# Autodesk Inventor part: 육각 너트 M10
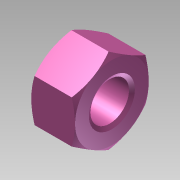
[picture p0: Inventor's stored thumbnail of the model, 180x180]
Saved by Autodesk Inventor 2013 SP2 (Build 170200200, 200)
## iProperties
Created: 2025-04
Part Number: 육각 너트 M10
Material: Generic
Document SubType Name: Modeling
Designer: i
Density: 1 g/cm^3
변환 표준: STEP AP214IS
전처리기: Build: 200, Release: 2013 SP2 Update 6 - Date: Thu 07/17/2014
전송 단위: 밀리미터
불확실성: 0.01
Author: i
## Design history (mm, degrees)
node "육각 너트 M101"
body "Solid1"
node "기준1"
